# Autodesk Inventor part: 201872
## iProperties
Created: 2007-10
Part Number: 201872
Document SubType Name: Modeling
Designer: TH
Density: 7.85 g/cm^3
Mass: 137.687 g
Surface Area: 88.4986 cm^2
Volume: 17.5397 cm^3
Material: Steel
Description: PIVOT ROD
Component Category: Lower Component
Author: TH
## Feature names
1. Extrusion1
2. Chamfer1
